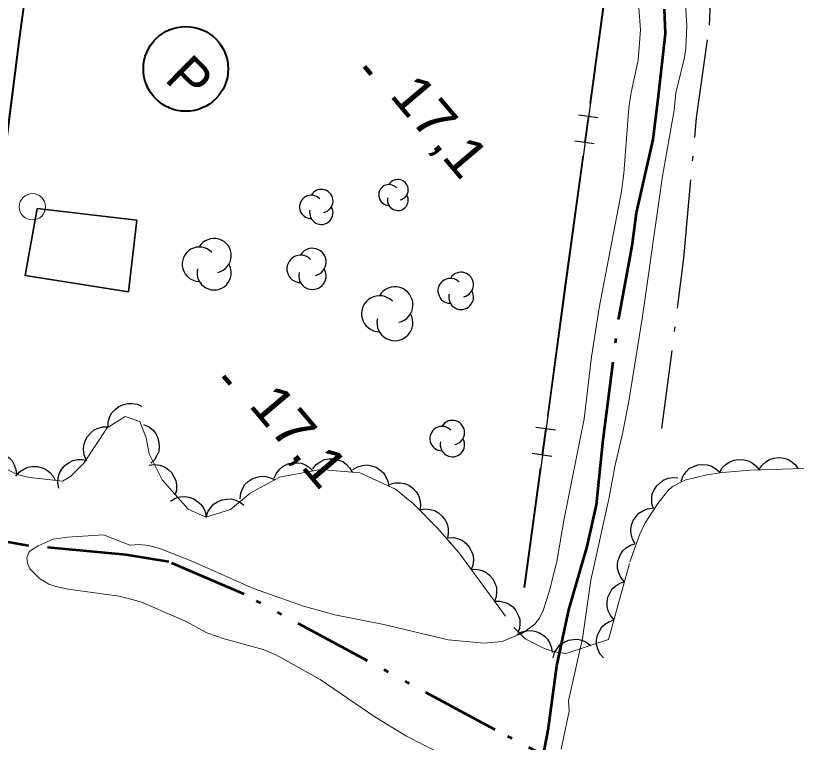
# Model space of a CAD drawing. Extents: x 386081 to 389416, y 5130568 to 5134082.
# Drawn here: x 387712.3 to 387771.9, y 5132200.4 to 5132255.7 of the extents above; entities that cross this region are included whole.
import ezdxf

# ---------------------------------------------------------------- set-up
doc = ezdxf.new("R2010")
doc.units = 0
doc.header["$LTSCALE"] = 1.2
for name, pattern in [('DASH_DOUBLE_DOT', [9.2, 5, -1.2, 0.3, -1.2, 0.3, -1.2]), ('DOT_DASHED', [7.7, 5, -1.2, 0.3, -1.2]), ('LONG_DASHED', [7.5, 6, -1.5])]:
    doc.linetypes.add(name, pattern=pattern)
for name, color, linetype, lineweight in [('2', 7, 'Continuous', 13), ('3', 7, 'Continuous', 140), ('31', 7, 'Continuous', 70), ('36', 7, 'Continuous', 13), ('37', 7, 'Continuous', 13), ('38', 7, 'Continuous', 40), ('4', 7, 'DASH_DOUBLE_DOT', 53), ('41', 7, 'DOT_DASHED', 25), ('44', 7, 'Continuous', 25)]:
    doc.layers.add(name, color=color, linetype=linetype, lineweight=lineweight)

msp = doc.modelspace()

# ---------------------------------------------------------------- linework, layer by layer
at = {"layer": '2'}
for points in [[(387754.4, 5132203.55), (387755.45, 5132208.28), (387756.09, 5132212.72), (387757.49, 5132219.03), (387757.91, 5132221.38), (387758.53, 5132224), (387758.98, 5132226.36), (387760.02, 5132232.8), (387761.54, 5132243.47), (387762.42, 5132248.5), (387762.55, 5132249.8), (387763.22, 5132252.51), (387763.31, 5132253.18), (387763.38, 5132254.92), (387763.18, 5132258.3)], [(387759.74, 5132256.29), (387759.86, 5132254.61), (387759.69, 5132252.3), (387759.16, 5132249.84), (387758.99, 5132248.67), (387758.6, 5132243.66), (387758.43, 5132242.3), (387756.71, 5132233.46), (387756.13, 5132229.72), (387755.57, 5132225.01), (387754.03, 5132217.26), (387753.51, 5132214.15), (387752.91, 5132211.83), (387752.46, 5132210.42), (387752.18, 5132209.83), (387751.82, 5132209.37), (387750.88, 5132208.7), (387749.33, 5132208.07), (387747.98, 5132207.93), (387745.24, 5132208.2), (387740.34, 5132209.36), (387736.62, 5132210.09), (387734.22, 5132210.76), (387730.41, 5132212.09), (387725.67, 5132214.2), (387723.42, 5132215.08), (387722.46, 5132215.36), (387721.75, 5132215.43), (387721.02, 5132215.4), (387719.02, 5132216.17)]]:
    msp.add_lwpolyline(points, dxfattribs=at)
at = {"layer": '2', "linetype": 'LONG_DASHED'}
for points in [[(387719.02, 5132216.17), (387716.26, 5132216), (387715.17, 5132215.84), (387714.04, 5132215.34), (387713.36, 5132214.9), (387713.18, 5132214.43), (387713.22, 5132214.01), (387713.4, 5132213.59), (387714.15, 5132212.86), (387714.86, 5132212.42), (387715.39, 5132212.24), (387716.33, 5132212.04), (387720.21, 5132211.51), (387721.85, 5132211.09), (387725.31, 5132209.58), (387726.86, 5132208.71), (387728.2, 5132208.26), (387731.16, 5132207.46), (387732.13, 5132207.05), (387735.49, 5132205.17), (387739.64, 5132202.33), (387742.06, 5132200.86), (387744.64, 5132199.53)], [(387753.84, 5132199.87), (387754.43, 5132202.76), (387754.4, 5132203.55)]]:
    msp.add_lwpolyline(points, dxfattribs=at)
at = {"layer": '3'}
for p, q in [((387738.87, 5132251.82), (387739.38, 5132251.21)), ((387728.15, 5132228.24), (387728.66, 5132227.63))]:
    msp.add_line(p, q, dxfattribs=at)
at = {"layer": '31', "lineweight": 35}
msp.add_lwpolyline([(387713.96, 5132241.01), (387721.54, 5132240.11), (387720.9, 5132234.68), (387713.04, 5132235.9)], close=True, dxfattribs=at)
at = {"layer": '36'}
msp.add_circle((387713.598, 5132241.14), 1, dxfattribs=at)
at = {"layer": '37', "lineweight": 25}
for p, q in [((387713.99, 5132264.36), (387712.65, 5132254.45)), ((387757.41, 5132258.91), (387751.05, 5132212.17)), ((387757.36, 5132258.92), (387756.01, 5132249.01)), ((387756.62, 5132247.92), (387755.14, 5132248.12)), ((387755.88, 5132248.02), (387755.61, 5132246.04)), ((387756.35, 5132245.93), (387754.87, 5132246.14)), ((387755.47, 5132245.05), (387754.12, 5132235.14)), ((387754.12, 5132235.14), (387752.78, 5132225.23)), ((387753.39, 5132224.13), (387751.9, 5132224.34)), ((387752.64, 5132224.24), (387752.37, 5132222.26)), ((387753.12, 5132222.15), (387751.63, 5132222.36)), ((387752.24, 5132221.27), (387751, 5132212.18))]:
    msp.add_line(p, q, dxfattribs=at)
for points in [[(387715.91, 5132278.22), (387712.65, 5132254.09), (387708.7, 5132223.12)], [(387712.65, 5132254.45), (387712.6, 5132254.1), (387711.38, 5132244.53)]]:
    msp.add_lwpolyline(points, dxfattribs=at)
at = {"layer": '38'}
msp.add_circle((387725.27, 5132251.63), 3.226, dxfattribs=at)
at = {"layer": '4'}
for points in [[(387752.48, 5132199.45), (387752.83, 5132201.32), (387753.51, 5132206.21), (387754.41, 5132210.47), (387755.81, 5132215.3), (387756.51, 5132218.47), (387757.02, 5132223.4), (387758.23, 5132232.78), (387759.23, 5132238.17), (387759.57, 5132240.69), (387760.83, 5132246.26), (387761.24, 5132249.55), (387761.77, 5132254.33), (387761.68, 5132256.17)], [(387827.96, 5132155.87), (387814.58, 5132166.24), (387802.51, 5132174.13), (387789.15, 5132181.05), (387776.27, 5132187.01), (387748.82, 5132201.34), (387729.71, 5132211.65), (387723.99, 5132214.11), (387720.73, 5132214.66), (387713.02, 5132215.38), (387710.32, 5132215.86)]]:
    msp.add_lwpolyline(points, dxfattribs=at)
at = {"layer": '41'}
msp.add_lwpolyline([(387761.5, 5132224.26), (387763.16, 5132237.22), (387764.13, 5132247.91), (387765.11, 5132254.97), (387765.47, 5132261.65), (387766.24, 5132270.1)], dxfattribs=at)
at = {"layer": '44'}
for points in [[(387719.36, 5132224.37), (387719.37, 5132224.78), (387719.5, 5132225.17), (387719.65, 5132225.47), (387719.89, 5132225.72), (387720.18, 5132225.95), (387720.54, 5132226.09), (387720.85, 5132226.18), (387721.2, 5132226.18), (387721.57, 5132226.11), (387721.9, 5132225.96)], [(387722.05, 5132224.58), (387722.44, 5132224.42), (387722.75, 5132224.16), (387722.97, 5132223.91), (387723.12, 5132223.6), (387723.23, 5132223.24), (387723.24, 5132222.86), (387723.21, 5132222.53), (387723.07, 5132222.21), (387722.88, 5132221.89), (387722.62, 5132221.64)], [(387717.69, 5132221.88), (387717.53, 5132222.27), (387717.49, 5132222.67), (387717.5, 5132223), (387717.61, 5132223.34), (387717.78, 5132223.66), (387718.04, 5132223.94), (387718.29, 5132224.16), (387718.61, 5132224.3), (387718.97, 5132224.39), (387719.33, 5132224.39)], [(387709.73, 5132222.2), (387710.1, 5132222.4), (387710.5, 5132222.48), (387710.83, 5132222.5), (387711.17, 5132222.42), (387711.51, 5132222.27), (387711.82, 5132222.04), (387712.05, 5132221.82), (387712.22, 5132221.51), (387712.34, 5132221.16), (387712.38, 5132220.8)], [(387715.6, 5132219.74), (387715.53, 5132220.15), (387715.57, 5132220.55), (387715.65, 5132220.87), (387715.83, 5132221.18), (387716.07, 5132221.46), (387716.39, 5132221.68), (387716.67, 5132221.83), (387717.02, 5132221.9), (387717.39, 5132221.91), (387717.74, 5132221.84)], [(387722.48, 5132221.48), (387722.89, 5132221.53), (387723.3, 5132221.47), (387723.61, 5132221.37), (387723.9, 5132221.17), (387724.17, 5132220.92), (387724.37, 5132220.59), (387724.52, 5132220.3), (387724.56, 5132219.95), (387724.56, 5132219.58), (387724.47, 5132219.23)], [(387732, 5132220.48), (387732.16, 5132220.86), (387732.42, 5132221.18), (387732.67, 5132221.4), (387732.99, 5132221.55), (387733.34, 5132221.65), (387733.72, 5132221.66), (387734.05, 5132221.63), (387734.37, 5132221.5), (387734.69, 5132221.3), (387734.94, 5132221.05)], [(387734.94, 5132221.21), (387735.2, 5132221.54), (387735.54, 5132221.76), (387735.83, 5132221.91), (387736.18, 5132221.97), (387736.55, 5132221.97), (387736.92, 5132221.87), (387737.22, 5132221.76), (387737.5, 5132221.54), (387737.75, 5132221.26), (387737.92, 5132220.95)], [(387737.97, 5132221.14), (387738.33, 5132221.36), (387738.72, 5132221.46), (387739.05, 5132221.5), (387739.4, 5132221.44), (387739.75, 5132221.32), (387740.06, 5132221.1), (387740.31, 5132220.89), (387740.5, 5132220.6), (387740.64, 5132220.25), (387740.71, 5132219.9)], [(387762.95, 5132220.27), (387763.1, 5132220.66), (387763.35, 5132220.98), (387763.58, 5132221.22), (387763.89, 5132221.38), (387764.24, 5132221.5), (387764.62, 5132221.52), (387764.95, 5132221.51), (387765.28, 5132221.39), (387765.6, 5132221.21), (387765.87, 5132220.97)], [(387765.88, 5132220.9), (387766.09, 5132221.27), (387766.38, 5132221.55), (387766.65, 5132221.74), (387766.98, 5132221.86), (387767.35, 5132221.92), (387767.73, 5132221.88), (387768.05, 5132221.82), (387768.36, 5132221.65), (387768.65, 5132221.42), (387768.87, 5132221.14)], [(387768.88, 5132221.11), (387769.1, 5132221.46), (387769.41, 5132221.73), (387769.68, 5132221.91), (387770.02, 5132222.01), (387770.39, 5132222.06), (387770.77, 5132222), (387771.08, 5132221.93), (387771.38, 5132221.74), (387771.66, 5132221.5), (387771.87, 5132221.21)], [(387712.35, 5132220.64), (387712.62, 5132220.96), (387712.96, 5132221.18), (387713.26, 5132221.32), (387713.61, 5132221.38), (387713.98, 5132221.37), (387714.35, 5132221.27), (387714.65, 5132221.15), (387714.92, 5132220.92), (387715.17, 5132220.65), (387715.34, 5132220.33)], [(387729.41, 5132218.92), (387729.45, 5132219.34), (387729.6, 5132219.72), (387729.77, 5132220), (387730.02, 5132220.24), (387730.33, 5132220.45), (387730.69, 5132220.57), (387731.01, 5132220.65), (387731.36, 5132220.62), (387731.72, 5132220.52), (387732.04, 5132220.36)], [(387760.86, 5132218.15), (387760.73, 5132218.54), (387760.72, 5132218.95), (387760.76, 5132219.28), (387760.9, 5132219.6), (387761.1, 5132219.91), (387761.38, 5132220.17), (387761.64, 5132220.37), (387761.97, 5132220.48), (387762.34, 5132220.54), (387762.7, 5132220.52)], [(387740.79, 5132220.03), (387741.19, 5132220.14), (387741.59, 5132220.14), (387741.92, 5132220.09), (387742.24, 5132219.95), (387742.54, 5132219.74), (387742.79, 5132219.45), (387742.98, 5132219.18), (387743.08, 5132218.85), (387743.13, 5132218.48), (387743.1, 5132218.12)], [(387724.1, 5132218.74), (387724.46, 5132218.96), (387724.85, 5132219.06), (387725.18, 5132219.1), (387725.53, 5132219.04), (387725.88, 5132218.92), (387726.19, 5132218.7), (387726.44, 5132218.49), (387726.63, 5132218.19), (387726.77, 5132217.85), (387726.83, 5132217.5)], [(387726.83, 5132217.52), (387726.95, 5132217.92), (387727.17, 5132218.26), (387727.39, 5132218.51), (387727.69, 5132218.7), (387728.03, 5132218.84), (387728.41, 5132218.9), (387728.73, 5132218.91), (387729.07, 5132218.82), (387729.41, 5132218.66), (387729.69, 5132218.44)], [(387743.06, 5132218.07), (387743.47, 5132218.15), (387743.87, 5132218.1), (387744.19, 5132218.02), (387744.49, 5132217.84), (387744.78, 5132217.6), (387745, 5132217.29), (387745.15, 5132217.01), (387745.22, 5132216.66), (387745.24, 5132216.29), (387745.17, 5132215.94)], [(387759.46, 5132215.49), (387759.25, 5132215.85), (387759.16, 5132216.25), (387759.12, 5132216.58), (387759.19, 5132216.92), (387759.32, 5132217.27), (387759.54, 5132217.58), (387759.75, 5132217.83), (387760.05, 5132218.01), (387760.4, 5132218.15), (387760.75, 5132218.2)], [(387745.21, 5132215.96), (387745.63, 5132215.98), (387746.02, 5132215.88), (387746.32, 5132215.75), (387746.6, 5132215.53), (387746.84, 5132215.25), (387747.01, 5132214.91), (387747.13, 5132214.6), (387747.15, 5132214.25), (387747.1, 5132213.88), (387746.98, 5132213.55)], [(387758.64, 5132212.6), (387758.37, 5132212.92), (387758.21, 5132213.29), (387758.12, 5132213.61), (387758.12, 5132213.96), (387758.19, 5132214.32), (387758.35, 5132214.67), (387758.52, 5132214.95), (387758.78, 5132215.18), (387759.1, 5132215.38), (387759.44, 5132215.5)], [(387746.98, 5132213.55), (387747.4, 5132213.56), (387747.79, 5132213.46), (387748.1, 5132213.33), (387748.37, 5132213.11), (387748.62, 5132212.83), (387748.79, 5132212.49), (387748.9, 5132212.19), (387748.92, 5132211.83), (387748.88, 5132211.47), (387748.76, 5132211.13)], [(387757.85, 5132209.71), (387757.58, 5132210.03), (387757.41, 5132210.4), (387757.32, 5132210.72), (387757.33, 5132211.07), (387757.39, 5132211.43), (387757.55, 5132211.78), (387757.72, 5132212.06), (387757.99, 5132212.29), (387758.3, 5132212.49), (387758.64, 5132212.6)], [(387748.76, 5132211.13), (387749.17, 5132211.14), (387749.57, 5132211.04), (387749.87, 5132210.91), (387750.15, 5132210.69), (387750.39, 5132210.41), (387750.56, 5132210.07), (387750.68, 5132209.77), (387750.69, 5132209.41), (387750.65, 5132209.05), (387750.53, 5132208.71)], [(387757.05, 5132206.82), (387756.78, 5132207.13), (387756.62, 5132207.51), (387756.53, 5132207.82), (387756.53, 5132208.18), (387756.6, 5132208.54), (387756.76, 5132208.89), (387756.93, 5132209.17), (387757.19, 5132209.4), (387757.51, 5132209.59), (387757.85, 5132209.71)], [(387750.46, 5132208.58), (387750.83, 5132208.79), (387751.23, 5132208.87), (387751.56, 5132208.9), (387751.9, 5132208.82), (387752.24, 5132208.69), (387752.55, 5132208.46), (387752.79, 5132208.24), (387752.96, 5132207.93), (387753.09, 5132207.58), (387753.14, 5132207.23)], [(387753.21, 5132206.82), (387753.32, 5132207.22), (387753.54, 5132207.56), (387753.76, 5132207.82), (387754.05, 5132208.01), (387754.39, 5132208.15), (387754.77, 5132208.21), (387755.1, 5132208.23), (387755.44, 5132208.14), (387755.77, 5132207.98), (387756.06, 5132207.76)]]:
    msp.add_lwpolyline(points, dxfattribs=at)
at = {"layer": '44', "linetype": 'DOT_DASHED', "lineweight": 13}
msp.add_lwpolyline([(387709.83, 5132222.15), (387712.42, 5132220.78), (387713.41, 5132220.53), (387715.9, 5132220.27), (387716.52, 5132220.64), (387717.52, 5132221.62), (387719.28, 5132224.32), (387720.65, 5132225.18), (387721.77, 5132224.8), (387722.25, 5132223.57), (387722.49, 5132222.33), (387723.47, 5132220.36), (387725.44, 5132218.13), (387726.8, 5132217.51), (387728.67, 5132218.11), (387730.17, 5132219.34), (387732.41, 5132220.56), (387735.52, 5132221.16), (387738.5, 5132220.9), (387741.23, 5132219.66), (387742.59, 5132218.54), (387744.43, 5132216.68), (387746.04, 5132214.83), (387750.22, 5132209.13), (387751.08, 5132208.27), (387752.56, 5132207.52), (387753.31, 5132207.27), (387754.18, 5132207.14), (387757.44, 5132208.22), (387759.06, 5132214.12), (387759.81, 5132216.22), (387760.2, 5132217.04), (387761.19, 5132218.57), (387761.91, 5132219.5), (387762.3, 5132219.86), (387763.24, 5132220.34), (387764.92, 5132220.74), (387766.11, 5132220.92), (387768.23, 5132221.09), (387772.28, 5132221.22)], dxfattribs=at)
at = {"layer": '44'}
for centre, radius, start, end in [((387741.409, 5132242.431), 0.787, 282.26917, 149.72626), ((387735.582, 5132241.576), 0.891, 282.26917, 149.72626), ((387740.732, 5132242.038), 0.787, 44.11537, 269.80396), ((387734.816, 5132241.13), 0.891, 44.11537, 269.80396), ((387741.409, 5132241.645), 0.787, 166.93686, 29.62122), ((387735.582, 5132240.684), 0.891, 166.93686, 29.62122), ((387727.426, 5132237.423), 1.306, 282.26917, 149.72626), ((387726.302, 5132236.77), 1.306, 44.11537, 269.80396), ((387734.906, 5132236.936), 1.044, 282.26917, 149.72626), ((387734.008, 5132236.414), 1.044, 44.11537, 269.80396), ((387727.426, 5132236.117), 1.306, 166.93686, 29.62122), ((387734.906, 5132235.892), 1.044, 166.93686, 29.62122), ((387746.216, 5132235.215), 0.947, 282.26917, 149.72626), ((387745.401, 5132234.742), 0.947, 44.11537, 269.80396), ((387741.181, 5132233.684), 1.367, 282.26917, 149.72626), ((387746.216, 5132234.268), 0.947, 166.93686, 29.62122), ((387740.005, 5132233.001), 1.367, 44.11537, 269.80396), ((387741.181, 5132232.318), 1.367, 166.93686, 29.62122), ((387745.556, 5132223.963), 0.925, 282.26917, 149.72626), ((387744.761, 5132223.501), 0.925, 44.11537, 269.80396), ((387745.556, 5132223.039), 0.925, 166.93686, 29.62122)]:
    msp.add_arc(centre, radius, start, end, dxfattribs=at)

# ---------------------------------------------------------------- texts
at = {"layer": '3', "width": 1.1}
for p in [(387740.7, 5132249.6), (387729.98, 5132226.02)]:
    msp.add_text('17,1   ', height=3, rotation=310.294, dxfattribs=at).set_placement(p)
at = {"layer": '38'}
msp.add_text('P', height=3, rotation=315.272, dxfattribs=at).set_placement((387723.56, 5132250.79))

doc.saveas('drawing.dxf')
